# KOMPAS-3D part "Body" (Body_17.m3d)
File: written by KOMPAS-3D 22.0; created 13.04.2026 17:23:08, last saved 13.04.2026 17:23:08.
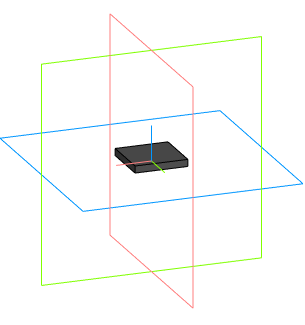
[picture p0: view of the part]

Document properties: Автор: Andrey; Полное имя файла: C:\Users\User1\Documents\Body_17.m3d

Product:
- Part/product: Body

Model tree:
1. Операция без истории:1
